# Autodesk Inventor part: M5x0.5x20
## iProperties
IsCustomPart: 0
Company: 한국ATC센터
Created: 2014-07
Part Number: M5x0.5x20
Material: Steel, Mild
Description: 6각머리 태핑 나사
Document SubType Name: Modeling
Standard: KS B 1003
Designer: KYOUNG IL JANG
Standards Organization: KS
Language: ko-KR
Size Designation: M 5 x 20
Categories: <MemberInstance><Categories><Category DisplayName="조임쇠" InternalName="e4da775c-781d-43d5-af7c-5136215cf5a6" Mnemonic="FSTN"><Category DisplayName="볼트" InternalN
Density: 1 g/cm^3
Author: KYOUNG IL JANG
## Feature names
1. Fillet2
